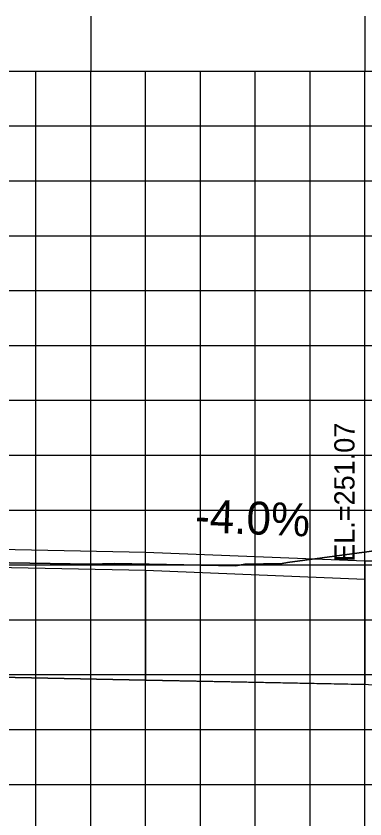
# Model space of a CAD drawing. Extents: x 859129 to 859299, y 366268 to 366378.
# Drawn here: x 859221.1 to 859227.46, y 366343.61 to 366358.24 of the extents above; entities that cross this region are included whole.
import ezdxf

# ---------------------------------------------------------------- set-up
doc = ezdxf.new("R2010")
doc.units = 0
for name, color, linetype in [('ANNOTATION', 7, 'Continuous'), ('D_Roadway_Drive_Gravel_RT', 7, 'Continuous'), ('D_Roadway_Edge_Shoulder', 7, 'Continuous'), ('D_Roadway_SubGrade', 7, 'Continuous'), ('D_Text_Standard', 7, 'Continuous'), ('JUNK COM EXC', 7, 'Continuous'), ('MAJOR', 7, 'Continuous'), ('MINOR', 7, 'Continuous'), ('S_Roadway_Centerline', 7, 'Continuous')]:
    doc.layers.add(name, color=color, linetype=linetype)

msp = doc.modelspace()

# ---------------------------------------------------------------- linework, layer by layer
at = {"layer": 'D_Roadway_Drive_Gravel_RT'}
msp.add_line((859227.464, 366348.311), (859237.51, 366348.231), dxfattribs=at)
at = {"layer": 'D_Roadway_Edge_Shoulder'}
msp.add_line((859227.462, 366348.31), (859227.462, 366347.977), dxfattribs=at)
msp.add_lwpolyline([(859197.466, 366348.311), (859201.462, 366348.47), (859212.462, 366348.69), (859223.462, 366348.47), (859227.464, 366348.311)], dxfattribs=at)
at = {"layer": 'D_Roadway_SubGrade'}
for points in [[(859201.462, 366346.137), (859201.462, 366348.137), (859212.462, 366348.357), (859223.462, 366348.137), (859223.462, 366346.137), (859212.462, 366346.357)], [(859223.462, 366348.137), (859227.462, 366347.977), (859227.462, 366346.057), (859223.462, 366346.137)]]:
    msp.add_lwpolyline(points, close=True, dxfattribs=at)
at = {"layer": 'JUNK COM EXC'}
msp.add_lwpolyline([(859196.462, 366348.151), (859196.462, 366346.037), (859201.462, 366346.137), (859212.462, 366346.357), (859223.462, 366346.137), (859228.464, 366346.037), (859228.466, 366348.614), (859227.539, 366348.481), (859226.052, 366348.278), (859225.954, 366348.264), (859225.274, 366348.251), (859225.106, 366348.22), (859222.892, 366348.262), (859222.456, 366348.252), (859214.703, 366348.376), (859213.255, 366348.415), (859210.867, 366348.383), (859201.956, 366348.308), (859200.211, 366348.266), (859197.405, 366348.194), (859196.462, 366348.151)], dxfattribs=at)
at = {"layer": 'MAJOR'}
for p, q in [((859222.462, 366358.238), (859222.462, 366357.236)), ((859227.462, 366358.238), (859227.462, 366357.236)), ((859142.462, 366357.236), (859282.462, 366357.236)), ((859142.462, 366357.236), (859282.462, 366357.236)), ((859222.462, 366337.236), (859222.462, 366357.236)), ((859227.462, 366337.236), (859227.462, 366357.236)), ((859142.462, 366352.236), (859282.462, 366352.236)), ((859142.462, 366347.236), (859282.462, 366347.236))]:
    msp.add_line(p, q, dxfattribs=at)
at = {"layer": 'MINOR'}
for p, q in [((859221.462, 366337.236), (859221.462, 366357.236)), ((859223.462, 366337.236), (859223.462, 366357.236)), ((859224.462, 366337.236), (859224.462, 366357.236)), ((859225.462, 366337.236), (859225.462, 366357.236)), ((859226.462, 366337.236), (859226.462, 366357.236)), ((859142.462, 366356.236), (859282.462, 366356.236)), ((859142.462, 366355.236), (859282.462, 366355.236)), ((859142.462, 366354.236), (859282.462, 366354.236)), ((859142.462, 366353.236), (859282.462, 366353.236)), ((859142.462, 366351.236), (859282.462, 366351.236)), ((859142.462, 366350.236), (859282.462, 366350.236)), ((859142.462, 366349.236), (859282.462, 366349.236)), ((859142.462, 366348.236), (859282.462, 366348.236)), ((859142.462, 366346.236), (859282.462, 366346.236)), ((859142.462, 366345.236), (859282.462, 366345.236)), ((859142.462, 366344.236), (859282.462, 366344.236))]:
    msp.add_line(p, q, dxfattribs=at)
at = {"layer": 'S_Roadway_Centerline'}
msp.add_lwpolyline([(859169.353, 366346.993), (859173.61, 366346.883), (859175.658, 366347.011), (859183.025, 366347.23), (859192.828, 366347.969), (859193.405, 366348.01), (859197.405, 366348.194), (859200.211, 366348.266), (859201.956, 366348.308), (859210.867, 366348.383), (859213.255, 366348.415), (859214.703, 366348.376), (859222.456, 366348.252), (859222.892, 366348.262), (859225.106, 366348.22), (859225.274, 366348.251), (859225.954, 366348.264), (859226.052, 366348.278), (859227.539, 366348.481), (859228.478, 366348.616), (859228.625, 366348.643), (859229.051, 366348.623), (859249.622, 366347.669)], dxfattribs=at)

# ---------------------------------------------------------------- texts
at = {"layer": 'ANNOTATION'}
msp.add_text('-4.0%', height=0.6, rotation=357.7096, dxfattribs=at).set_placement((859224.357, 366348.835))
at = {"layer": 'D_Text_Standard'}
msp.add_text(' EL.=251.07', height=0.36848, rotation=90, dxfattribs=at).set_placement((859227.273, 366348.156))

doc.saveas('drawing.dxf')
